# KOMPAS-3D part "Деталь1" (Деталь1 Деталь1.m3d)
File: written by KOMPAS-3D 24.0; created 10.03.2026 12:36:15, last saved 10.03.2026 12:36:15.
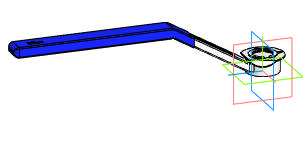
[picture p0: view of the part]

Document properties: Автор: R2D2; Полное имя файла: E:\Работа\Зайцев\BV3232P(4pc)-FP-3WL-F-ISO-H Кран шаровой DN.ru Ду15-100 Ру16\DN40\исходные материалы\Деталь1 Деталь1.m3d

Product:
- Body: Твердое тело1  | qty 1
- Part/product: Деталь1
    additional columns: Типовые

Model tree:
1. Твердое тело1  (labels: Твердое тело1)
